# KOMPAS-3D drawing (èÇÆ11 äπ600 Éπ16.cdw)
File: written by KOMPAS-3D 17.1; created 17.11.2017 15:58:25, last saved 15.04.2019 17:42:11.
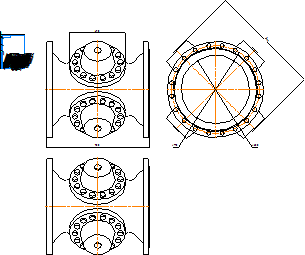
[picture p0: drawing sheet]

Sheet 1: A4, portrait

Title block, sheet 1: name: КАТ11 Ду600 Ру16; material: Внимание! Данный продукт является объектом авторского права ООО «Торговый Дом АДЛ». / Запрещается изменение, копирование, распространение / (в том числе путем копирования на другие сайты и ресурсы в Интернете) / или любое иное использование информации и объектов без предварительного / согласия правообладателя (ООО «Торговый Дом АДЛ»).; mass: 12,4; sheets: 1; organisation: ООО "Торговый дом АДЛ"; sheet format: A4; stored path: \\adlc.lan\data\АДЛ_ПКД\3D-модели\ADL production\Клапаны КАТ ГРАНРЕГ\КАТ11\KOMPAS 2D\КАТ11 Ду600 Ру16.cdw

Views: Вид 1, Проекционный вид 2, Проекционный вид 3
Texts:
  kka
  adl
Dimensions and other numbers on the sheet: 490; 900; 770; 970; 600; 1:1; 1; 12,4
